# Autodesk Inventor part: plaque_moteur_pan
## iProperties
Created: 2011-01
Part Number: plaque_moteur_pan
Document SubType Name: Modeling
Designer: eric
Density: 1 g/cm^3
Mass: 5.66225 g
Surface Area: 82.8643 cm^2
Volume: 5.66225 cm^3
Author: eric
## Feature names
1. Base1
